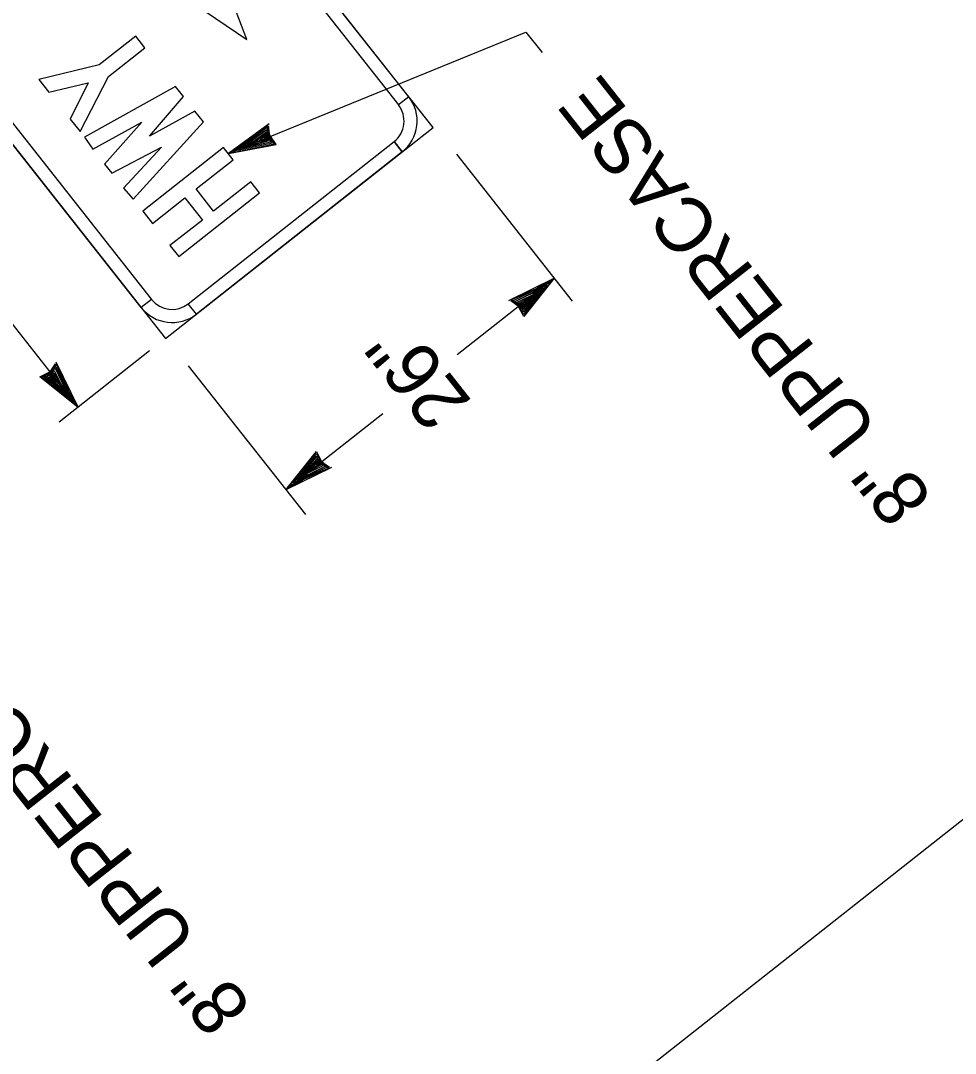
# Model space of a CAD drawing. Extents: x 671946 to 673995, y 1673066 to 1674936.
# Drawn here: x 672677.9 to 672749.2, y 1673527.2 to 1673606 of the extents above; entities that cross this region are included whole.
import ezdxf

# ---------------------------------------------------------------- set-up
doc = ezdxf.new("R2010")
doc.units = 0
doc.layers.add('C-ANNO-SYMB', color=7, linetype='Continuous')
doc.layers.add('Level 1', color=7, linetype='Continuous')

msp = doc.modelspace()

# ---------------------------------------------------------------- linework, layer by layer
at = {"layer": 'C-ANNO-SYMB'}
for p, q in [((672709.345, 1673597.867), (672657.341, 1673663.833)), ((672658.413, 1673660.858), (672706.703, 1673599.603)), ((672707.488, 1673600.222), (672659.198, 1673661.477)), ((672636.923, 1673647.736), (672688.927, 1673581.77)), ((672639.565, 1673645.999), (672687.855, 1673584.745)), ((672687.07, 1673584.126), (672638.78, 1673645.38)), ((672695.138, 1673604.582), (672692.225, 1673612.308)), ((672688.305, 1673609.218), (672695.138, 1673604.582)), ((672695.138, 1673604.582), (672695.138, 1673604.582)), ((672695.138, 1673604.582), (672695.138, 1673604.582)), ((672695.181, 1673604.527), (672695.181, 1673604.527)), ((672695.181, 1673604.527), (672695.181, 1673604.527)), ((672707.488, 1673600.222), (672706.703, 1673599.603)), ((672707.488, 1673600.222), (672706.703, 1673599.603)), ((672706.703, 1673599.603), (672706.703, 1673599.603)), ((672706.703, 1673599.603), (672706.703, 1673599.603)), ((672688.927, 1673581.77), (672709.345, 1673597.867)), ((672709.345, 1673597.867), (672709.345, 1673597.867)), ((672709.345, 1673597.867), (672709.345, 1673597.867)), ((672690.664, 1673584.413), (672706.37, 1673596.795)), ((672706.37, 1673596.795), (672706.99, 1673596.009)), ((672706.99, 1673596.009), (672706.37, 1673596.795)), ((672706.99, 1673596.009), (672691.283, 1673583.627)), ((672687.855, 1673584.745), (672687.07, 1673584.126)), ((672687.855, 1673584.745), (672687.07, 1673584.126)), ((672691.283, 1673583.627), (672690.664, 1673584.413)), ((672690.664, 1673584.413), (672690.664, 1673584.413)), ((672690.664, 1673584.413), (672690.664, 1673584.413)), ((672691.283, 1673583.627), (672690.664, 1673584.413))]:
    msp.add_line(p, q, dxfattribs=at)
for points in [[(672680.028, 1673600.577), (672683.028, 1673601.279), (672681.661, 1673598.505), (672682.404, 1673597.562), (672684.564, 1673601.753), (672687.356, 1673603.954), (672686.655, 1673604.843), (672683.864, 1673602.642), (672679.269, 1673601.539)], [(672691.819, 1673598.292), (672691.171, 1673599.115), (672687.701, 1673597.2), (672690.295, 1673600.226), (672689.695, 1673600.986), (672682.744, 1673597.131), (672683.378, 1673596.223), (672687.12, 1673598.286), (672684.28, 1673595.079), (672684.827, 1673594.384), (672688.623, 1673596.379), (672685.725, 1673593.246), (672686.466, 1673592.41)], [(672696.094, 1673592.87), (672695.428, 1673593.715), (672692.6, 1673591.486), (672691.266, 1673593.178), (672694.094, 1673595.407), (672693.352, 1673596.348), (672687.19, 1673591.491), (672687.933, 1673590.549), (672690.404, 1673592.497), (672691.737, 1673590.806), (672689.266, 1673588.858), (672689.933, 1673588.013)]]:
    msp.add_lwpolyline(points, close=True, dxfattribs=at)
for centre, radius, start, end in [((672705.132, 1673598.365), 3, 308.25039, 38.2506), ((672705.132, 1673598.365), 2, 308.25039, 38.2506), ((672689.426, 1673585.983), 2, 218.25075, 308.25039), ((672689.426, 1673585.983), 3, 218.25075, 308.25039)]:
    msp.add_arc(centre, radius, start, end, dxfattribs=at)
at = {"layer": 'Level 1'}
for p, q in [((672825.472, 1673604.707), (672631.402, 1673451.711)), ((672682.255, 1673576.51), (672662.493, 1673601.577)), ((672696.843, 1673598.147), (672693.723, 1673595.878)), ((672696.664, 1673597.837), (672694.081, 1673595.983)), ((672696.707, 1673598.002), (672694.237, 1673596.082)), ((672696.671, 1673597.696), (672694.631, 1673596.29)), ((672696.671, 1673597.696), (672694.774, 1673596.296)), ((672696.744, 1673597.785), (672696.664, 1673597.837)), ((672696.922, 1673596.949), (672696.671, 1673597.696)), ((672696.972, 1673596.769), (672696.671, 1673597.696)), ((672696.727, 1673597.636), (672696.707, 1673598.002)), ((672696.79, 1673598.009), (672696.744, 1673597.785)), ((672696.897, 1673597.195), (672696.79, 1673598.009)), ((672694.631, 1673596.29), (672696.873, 1673596.867)), ((672696.64, 1673597.51), (672695.276, 1673596.522)), ((672695.276, 1673596.522), (672696.72, 1673596.886)), ((672696.599, 1673597.348), (672695.694, 1673596.739)), ((672695.694, 1673596.739), (672696.591, 1673596.913)), ((672696.758, 1673596.931), (672695.851, 1673596.837)), ((672696.593, 1673597.23), (672696.112, 1673596.899)), ((672696.112, 1673596.899), (672696.536, 1673596.976)), ((672696.517, 1673597.079), (672696.693, 1673597.39)), ((672696.536, 1673596.976), (672696.517, 1673597.079)), ((672696.591, 1673596.913), (672696.593, 1673597.23)), ((672696.72, 1673596.886), (672696.599, 1673597.348)), ((672696.873, 1673596.867), (672696.64, 1673597.51)), ((672696.693, 1673597.39), (672696.758, 1673596.931)), ((672696.888, 1673597.278), (672696.727, 1673597.636)), ((672697.378, 1673596.577), (672696.888, 1673597.278)), ((672697.238, 1673596.63), (672696.897, 1673597.195)), ((672697.088, 1673596.706), (672696.922, 1673596.949)), ((672693.723, 1673595.878), (672697.378, 1673596.577)), ((672694.033, 1673595.96), (672697.238, 1673596.63)), ((672694.237, 1673596.082), (672694.033, 1673595.96)), ((672694.081, 1673595.983), (672694.203, 1673596.153)), ((672694.203, 1673596.153), (672694.952, 1673596.662)), ((672694.441, 1673596.143), (672697.088, 1673596.706)), ((672694.952, 1673596.662), (672694.441, 1673596.143)), ((672694.774, 1673596.296), (672696.972, 1673596.769)), ((672695.168, 1673596.502), (672695.555, 1673596.79)), ((672695.645, 1673596.659), (672695.168, 1673596.502)), ((672695.851, 1673596.837), (672695.645, 1673596.659)), ((672711.123, 1673595.822), (672719.952, 1673584.622)), ((672711.196, 1673580.533), (672718.584, 1673586.357)), ((672715.122, 1673584.654), (672718.584, 1673586.357)), ((672715.315, 1673584.706), (672718.163, 1673585.998)), ((672715.48, 1673584.668), (672718.324, 1673586.09)), ((672718.584, 1673586.357), (672716.263, 1673583.449)), ((672718.366, 1673586.121), (672716.281, 1673583.597)), ((672718.015, 1673585.846), (672716.284, 1673583.766)), ((672718.117, 1673586.06), (672717.317, 1673585.635)), ((672717.317, 1673585.635), (672718.015, 1673585.846)), ((672718.324, 1673586.09), (672718.117, 1673586.06)), ((672718.163, 1673585.998), (672718.366, 1673586.121)), ((672715.601, 1673584.595), (672717.796, 1673585.746)), ((672715.601, 1673584.595), (672717.724, 1673585.622)), ((672715.78, 1673584.537), (672717.291, 1673585.283)), ((672717.796, 1673585.746), (672716.241, 1673584.031)), ((672717.724, 1673585.622), (672716.282, 1673583.897)), ((672717.291, 1673585.283), (672716.296, 1673584.175)), ((672717.358, 1673585.369), (672716.923, 1673585.161)), ((672716.997, 1673585.021), (672717.358, 1673585.369)), ((672715.94, 1673584.162), (672715.269, 1673584.636)), ((672715.269, 1673584.636), (672715.489, 1673584.572)), ((672715.629, 1673584.518), (672715.315, 1673584.706)), ((672715.489, 1673584.572), (672715.48, 1673584.668)), ((672716.146, 1673584.026), (672715.601, 1673584.595)), ((672716.282, 1673583.897), (672715.601, 1673584.595)), ((672715.87, 1673584.208), (672715.629, 1673584.518)), ((672716.241, 1673584.031), (672715.78, 1673584.537)), ((672716.219, 1673584.444), (672715.862, 1673584.433)), ((672715.862, 1673584.433), (672716.238, 1673584.162)), ((672715.943, 1673584.497), (672716.903, 1673585.014)), ((672716.296, 1673584.175), (672715.943, 1673584.497)), ((672716.05, 1673584.448), (672716.568, 1673584.719)), ((672716.332, 1673584.302), (672716.05, 1673584.448)), ((672716.302, 1673584.379), (672716.219, 1673584.444)), ((672716.238, 1673584.162), (672716.744, 1673584.92)), ((672716.568, 1673584.719), (672716.302, 1673584.379)), ((672716.903, 1673585.014), (672716.332, 1673584.302)), ((672716.744, 1673584.92), (672716.997, 1673585.021)), ((672716.263, 1673583.449), (672715.87, 1673584.208)), ((672716.281, 1673583.597), (672715.94, 1673584.162)), ((672716.284, 1673583.766), (672716.146, 1673584.026)), ((672687.715, 1673580.814), (672680.811, 1673575.371)), ((672680.06, 1673579.154), (672680.533, 1673579.824)), ((672680.416, 1673579.465), (672680.604, 1673579.779)), ((672680.533, 1673579.824), (672680.47, 1673579.605)), ((672680.47, 1673579.605), (672680.565, 1673579.613)), ((672680.551, 1673579.971), (672682.255, 1673576.51)), ((672680.565, 1673579.613), (672681.987, 1673576.769)), ((672680.604, 1673579.779), (672681.895, 1673576.93)), ((672690.658, 1673579.688), (672699.614, 1673568.328)), ((672679.346, 1673578.831), (672680.106, 1673579.223)), ((672682.255, 1673576.51), (672679.346, 1673578.831)), ((672679.495, 1673578.813), (672680.06, 1673579.154)), ((672682.019, 1673576.727), (672679.495, 1673578.813)), ((672679.663, 1673578.81), (672679.923, 1673578.948)), ((672681.743, 1673577.079), (672679.663, 1673578.81)), ((672679.795, 1673578.812), (672680.493, 1673579.492)), ((672681.52, 1673577.369), (672679.795, 1673578.812)), ((672679.923, 1673578.948), (672680.493, 1673579.492)), ((672679.928, 1673578.853), (672680.434, 1673579.313)), ((672681.644, 1673577.298), (672679.928, 1673578.853)), ((672680.331, 1673579.232), (672680.06, 1673578.856)), ((672680.06, 1673578.856), (672680.818, 1673578.35)), ((672680.073, 1673578.797), (672680.395, 1673579.151)), ((672681.181, 1673577.803), (672680.073, 1673578.797)), ((672680.106, 1673579.223), (672680.416, 1673579.465)), ((672680.2, 1673578.762), (672680.345, 1673579.043)), ((672680.912, 1673578.19), (672680.2, 1673578.762)), ((672680.277, 1673578.792), (672680.342, 1673578.874)), ((672680.616, 1673578.526), (672680.277, 1673578.792)), ((672680.342, 1673578.874), (672680.331, 1673579.232)), ((672680.345, 1673579.043), (672680.616, 1673578.526)), ((672680.395, 1673579.151), (672680.912, 1673578.19)), ((672680.434, 1673579.313), (672681.181, 1673577.803)), ((672680.493, 1673579.492), (672681.52, 1673577.369)), ((672680.493, 1673579.492), (672681.644, 1673577.298)), ((672680.818, 1673578.35), (672680.919, 1673578.097)), ((672680.919, 1673578.097), (672681.266, 1673577.735)), ((672681.266, 1673577.735), (672681.059, 1673578.171)), ((672681.958, 1673576.977), (672681.533, 1673577.776)), ((672681.533, 1673577.776), (672681.743, 1673577.079)), ((672681.895, 1673576.93), (672682.019, 1673576.727)), ((672681.987, 1673576.769), (672681.958, 1673576.977)), ((672698.119, 1673570.224), (672705.508, 1673576.048)), ((672698.119, 1673570.224), (672700.441, 1673573.133)), ((672698.337, 1673570.46), (672700.422, 1673572.984)), ((672698.688, 1673570.735), (672700.42, 1673572.816)), ((672698.907, 1673570.835), (672700.463, 1673572.55)), ((672698.979, 1673570.959), (672700.421, 1673572.684)), ((672700.42, 1673572.816), (672700.558, 1673572.555)), ((672700.421, 1673572.684), (672701.102, 1673571.986)), ((672700.422, 1673572.984), (672700.763, 1673572.419)), ((672700.441, 1673573.133), (672700.833, 1673572.373)), ((672700.463, 1673572.55), (672700.923, 1673572.044)), ((672700.558, 1673572.555), (672701.102, 1673571.986)), ((672701.581, 1673571.927), (672698.119, 1673570.224)), ((672701.223, 1673571.913), (672698.379, 1673570.492)), ((672701.389, 1673571.875), (672698.54, 1673570.583)), ((672701.102, 1673571.986), (672698.907, 1673570.835)), ((672701.102, 1673571.986), (672698.979, 1673570.959)), ((672699.413, 1673571.298), (672700.407, 1673572.406)), ((672700.923, 1673572.044), (672699.413, 1673571.298)), ((672699.96, 1673571.661), (672699.706, 1673571.56)), ((672699.8, 1673571.567), (672700.372, 1673572.279)), ((672700.76, 1673572.084), (672699.8, 1673571.567)), ((672700.466, 1673572.419), (672699.96, 1673571.661)), ((672700.136, 1673571.862), (672700.402, 1673572.202)), ((672700.653, 1673572.133), (672700.136, 1673571.862)), ((672700.372, 1673572.279), (672700.653, 1673572.133)), ((672700.402, 1673572.202), (672700.484, 1673572.137)), ((672700.407, 1673572.406), (672700.76, 1673572.084)), ((672700.841, 1673572.148), (672700.466, 1673572.419)), ((672700.484, 1673572.137), (672700.841, 1673572.148)), ((672700.763, 1673572.419), (672701.434, 1673571.946)), ((672700.833, 1673572.373), (672701.074, 1673572.063)), ((672701.074, 1673572.063), (672701.389, 1673571.875)), ((672701.434, 1673571.946), (672701.215, 1673572.009)), ((672701.215, 1673572.009), (672701.223, 1673571.913)), ((672698.586, 1673570.521), (672699.386, 1673570.946)), ((672699.386, 1673570.946), (672698.688, 1673570.735)), ((672699.706, 1673571.56), (672699.345, 1673571.212)), ((672699.345, 1673571.212), (672699.78, 1673571.42)), ((672698.54, 1673570.583), (672698.337, 1673570.46)), ((672698.379, 1673570.492), (672698.586, 1673570.521))]:
    msp.add_line(p, q, dxfattribs=at)
msp.add_lwpolyline([(672693.723, 1673595.878), (672716.436, 1673605.136), (672717.659, 1673603.585)], dxfattribs=at)

# ---------------------------------------------------------------- texts
for s, p in [('8" UPPERCASE', (672747.58, 1673569.637)), ('26"', (672712.374, 1673576.948)), ('8" UPPERCASE', (672695.612, 1673530.753))]:
    msp.add_text(s, height=4.2, rotation=128.25054, dxfattribs=at).set_placement(p)

doc.saveas('drawing.dxf')
